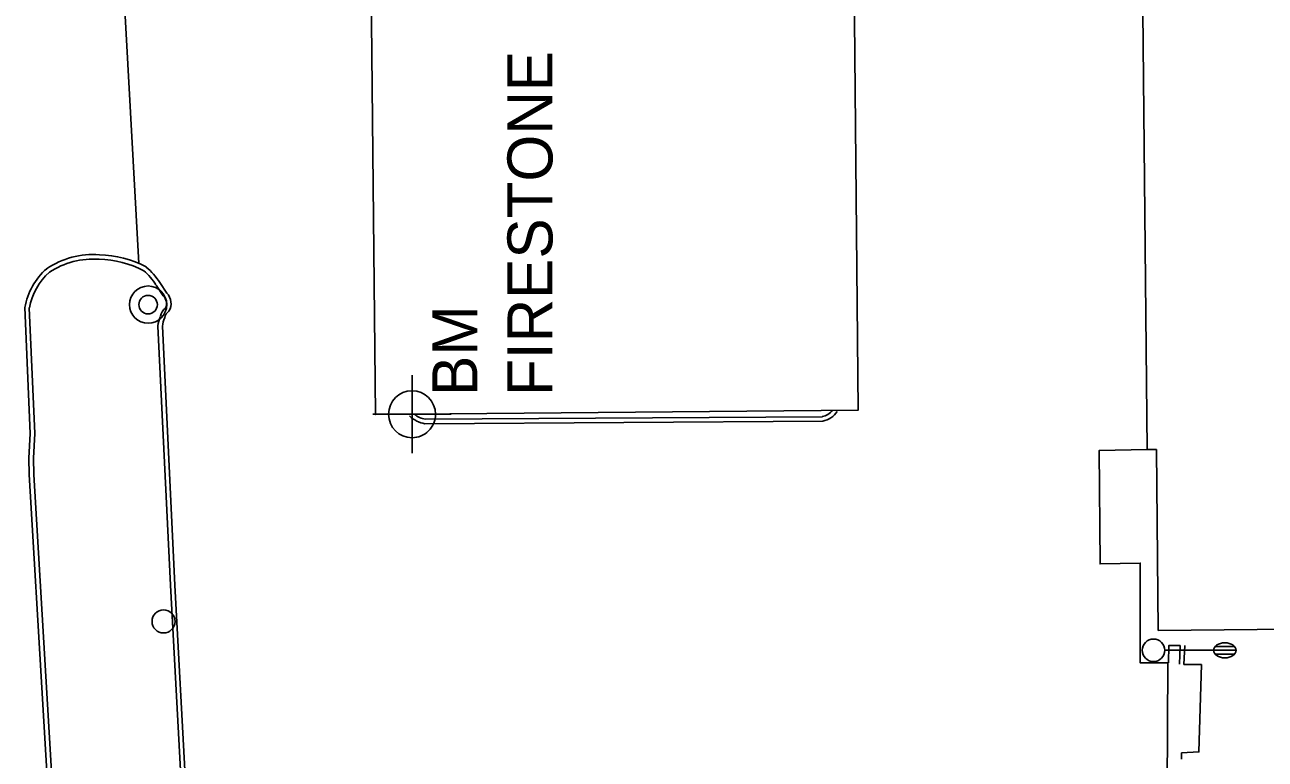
# Model space of a CAD drawing. Extents: x 2145380 to 2157287, y 139568 to 149130.
# Drawn here: x 2150960.5 to 2151125.7, y 145767 to 145864.8 of the extents above; entities that cross this region are included whole.
import ezdxf

# ---------------------------------------------------------------- set-up
doc = ezdxf.new("R2010")
doc.units = 0
for name, color, linetype in [('Default', 7, 'Continuous'), ('SURV_Benchmark', 7, 'Continuous'), ('TOPO_Asphalt', 7, 'Continuous'), ('TOPO_Building', 7, 'Continuous'), ('TOPO_Curb Back', 7, 'Continuous'), ('TOPO_Light Pole', 7, 'Continuous'), ('TOPO_San Manhole', 7, 'Continuous'), ('TOPO_Water Meter', 7, 'Continuous')]:
    doc.layers.add(name, color=color, linetype=linetype)

# ---------------------------------------------------------------- blocks, each defined once
blk = doc.blocks.new('LP')
at = {"layer": 'TOPO_Light Pole'}
blk.add_line((3.81, 0), (20.32, 0), dxfattribs=at)
for points in [[(20.32, 0), (27.94, 0)], [(20.32, 0), (23.5, 0)], [(20.83, 1.27), (27.43, 1.27)], [(20.83, 1.27), (23.5, 1.27)], [(23.71, 1.27), (27.43, 1.27)], [(23.71, 0), (27.94, 0)], [(20.83, -1.27), (27.43, -1.27)], [(20.83, -1.27), (23.5, -1.27)], [(23.71, -1.27), (27.43, -1.27)]]:
    blk.add_lwpolyline(points, dxfattribs=at)
blk.add_circle((0, 0), 3.81, dxfattribs=at)
blk.add_ellipse((24.13, 0), major_axis=(3.81, 0), ratio=0.666667, dxfattribs=at)
blk = doc.blocks.new('WTRMTR')
at = {"layer": 'Default'}
blk.add_circle((0, 0), 3.89, dxfattribs=at)
blk = doc.blocks.new('EXMHSS')
at = {"layer": 'Default'}
for radius in [6.3, 3.13]:
    blk.add_circle((0, 0), radius, dxfattribs=at)
blk = doc.blocks.new('BM')
at = {"layer": 'SURV_Benchmark'}
for p, q in [((0, 2.49), (0, 4.15)), ((-2.49, 0), (-4.16, 0)), ((4.16, 0), (2.49, 0)), ((0, -4.16), (0, -2.49))]:
    blk.add_line(p, q, dxfattribs=at)
for points in [[(0, 2.49), (0, 2.49), (0, 0), (2.49, 0), (2.49, 0), (2.49, 0)], [(0, 2.49), (0, 2.49), (0, 0), (2.49, 0), (2.49, 0), (2.49, 0), (2.49, 0)], [(-2.5, 0), (-2.49, 0), (0, 0), (0, -2.49), (0, -2.49)], [(-2.5, 0), (-2.49, 0), (0, 0), (0, -2.49), (0, -2.49)]]:
    blk.add_lwpolyline(points, dxfattribs=at)
for start, end in [(90.0638, 180.0068), (0.0638, 90.0068), (0.0638, 90.0068), (180.0638, 270.0068), (180.0638, 270.0068), (269.9472, 359.9927)]:
    blk.add_arc((0, 0), 2.5, start, end, dxfattribs=at)

msp = doc.modelspace()

# ---------------------------------------------------------------- linework, layer by layer
at = {"layer": 'TOPO_Asphalt'}
for points in [[(2150971.18, 145874.16), (2150973.51, 145873.27), (2150975.75, 145833.01)], [(2151114.39, 145782.17), (2151112.86, 145782.13), (2151112.81, 145779.85), (2151109.07, 145779.84), (2151109.07, 145793.12), (2151103.72, 145793.01), (2151103.61, 145808.13), (2151109.97, 145808.22)], [(2151024.44, 145718.43), (2151063.85, 145720.14), (2151064.05, 145715.1), (2151068.01, 145715.14), (2151067.85, 145720.06), (2151112.44, 145720.94), (2151112.74, 145779.85)], [(2151114.88, 145779.62), (2151117.21, 145779.6), (2151116.89, 145767.99), (2151114.57, 145767.84), (2151114.58, 145767.02)]]:
    msp.add_lwpolyline(points, dxfattribs=at)
at = {"layer": 'TOPO_Building'}
msp.add_lwpolyline([(2151171.94, 145881.01), (2151172.88, 145784.76), (2151111.47, 145784.16), (2151111.23, 145808.23), (2151109.97, 145808.22), (2151109.28, 145880.07), (2151070.88, 145879.7), (2151071.52, 145813.5), (2151007.23, 145812.88), (2151006.64, 145873.96), (2150993.06, 145873.83), (2150992.7, 145910.67), (2151014.52, 145910.88), (2151014.53, 145909.77), (2151156.7, 145911.15), (2151156.99, 145880.87)], close=True, dxfattribs=at)
at = {"layer": 'TOPO_Curb Back'}
for p, q in [((2151114.28, 145779.65), (2151114.39, 145782.17)), ((2151114.88, 145779.62), (2151114.99, 145782.14))]:
    msp.add_line(p, q, dxfattribs=at)
for points in [[(2150978.02, 145830.14), (2150978.99, 145828.68)], [(2150978.53, 145830.46), (2150979.46, 145829.07)], [(2150966.18, 145724.65), (2150964.77, 145743.68), (2150961.13, 145804.91), (2150961.1, 145807.1), (2150961.27, 145810.35), (2150960.55, 145827.14)], [(2150966.78, 145724.72), (2150965.37, 145743.72), (2150961.73, 145804.93), (2150961.7, 145807.09), (2150961.87, 145810.35), (2150961.15, 145827.1)], [(2150978.27, 145824.68), (2150979.94, 145790.17), (2150982.86, 145736.02), (2150983.72, 145717.39), (2151002.33, 145717.91), (2151022.79, 145718.09)], [(2150978.87, 145824.66), (2150980.54, 145790.2), (2150983.46, 145736.05), (2150984.3, 145718.01), (2151002.32, 145718.51), (2151022.78, 145718.69)], [(2151013.82, 145811.66), (2151066.8, 145812.01)], [(2151013.88, 145812.26), (2151066.74, 145812.61)]]:
    msp.add_lwpolyline(points, dxfattribs=at)
for centre, radius, start, end in [((2150969.67, 145823.06), 11.14, 85.8136, 123.8896), ((2150969.67, 145823.06), 10.54, 85.7339, 123.6839), ((2150970.14, 145820.11), 13.46, 62.3638, 88.6896), ((2150970.14, 145820.12), 14.06, 62.0875, 88.6274), ((2150969.26, 145825.65), 8.83, 131.0588, 170.277), ((2150969.26, 145825.65), 8.23, 131.3196, 169.839), ((2150970.98, 145825.74), 8.3, 32.0203, 49.4071), ((2150970.98, 145825.73), 8.9, 32.0803, 49.8437), ((2150978.02, 145827.68), 1.4, 333.4983, 46.1429), ((2150978.02, 145827.68), 2, 329.1792, 44.1131), ((2150980.51, 145825.55), 1.95, 129.4798, 167.4583), ((2150983.61, 145823.94), 5.4, 157.9325, 172.0912), ((2150983.61, 145823.94), 4.8, 157.2992, 171.4405), ((2150980.51, 145825.55), 1.35, 125.0323, 169.4461), ((2151014.49, 145815.49), 3.88, 225.7389, 260.1937), ((2151014.49, 145815.49), 3.28, 231.2791, 259.3018), ((2151066.28, 145814.85), 2.28, 281.5556, 322.7725), ((2151066.28, 145814.85), 2.88, 280.3235, 327.7705)]:
    msp.add_arc(centre, radius, start, end, dxfattribs=at)

# ---------------------------------------------------------------- block references
at = {"layer": 'SURV_Benchmark', "xscale": 1.25, "yscale": 1.25}
msp.add_blockref('BM', (2151012.11, 145812.94), dxfattribs=at)
at = {"layer": 'TOPO_Light Pole', "xscale": 0.39370000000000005, "yscale": 0.3937000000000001}
msp.add_blockref('LP', (2151110.83, 145781.51), dxfattribs=at)
at = {"layer": 'TOPO_San Manhole', "xscale": 0.39370000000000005, "yscale": 0.3937000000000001}
msp.add_blockref('EXMHSS', (2150976.97, 145827.53), dxfattribs=at)
at = {"layer": 'TOPO_Water Meter', "xscale": 0.39370000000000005, "yscale": 0.3937000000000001}
msp.add_blockref('WTRMTR', (2150979.02, 145785.35), dxfattribs=at)

# ---------------------------------------------------------------- texts
at = {"layer": 'SURV_Benchmark'}
for s, p in [('FIRESTONE', (2151030.81, 145815.38)), ('BM', (2151020.81, 145815.38))]:
    msp.add_text(s, height=6, rotation=90, dxfattribs=at).set_placement(p)

doc.saveas('drawing.dxf')
